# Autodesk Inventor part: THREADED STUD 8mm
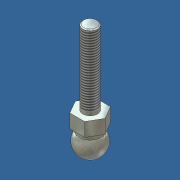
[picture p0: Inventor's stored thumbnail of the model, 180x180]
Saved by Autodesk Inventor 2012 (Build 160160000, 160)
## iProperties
Created: 2007-03
Part Number: THREADED STUD 8mm
Document SubType Name: Modeling
Designer: Andy Moles
Material: Steel
Mass: 40.6007 g
Surface Area: 22.6004 cm^2
Volume: 5.17207 cm^3
Density: 7.85 g/cm^3
Author: Andy Moles
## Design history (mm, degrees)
sketch "Sketch1"
  geometry: L1 (0, -7.5)-(0, 7.5); A1 r 7.5 centre (0, 0) between (0, -7.5) and (0, 7.5); 1 further point
  constraints: 2 end point, 2 point on circle, 1 centre point, 1 coincident, 1 midpoint, 1 vertical
  dimensions: "d5" = 15 distance of L1.start L1.end
revolve "Revolution1" sketch "Sketch1" stored, may be unused: angle "d1" = 90 deg
sketch "Sketch2"
  geometry: C1 r 6 at (0, 0); 1 further point
  constraints: 1 centre point, 1 coincident
  dimensions: "d2" = 12 diameter of C1
extrude "Extrusion1" join sketch "Sketch2" distance "d3" = 7; taper "d4" = 0 deg
sketch "Sketch3"
  geometry: L1 (-4.041, 7)-(4.041, 7); L2 (4.041, 7)-(8.083, 0); L3 (8.083, 0)-(4.041, -7); L4 (4.041, -7)-(-4.041, -7); L5 (-4.041, -7)-(-8.083, 0); L6 (-8.083, 0)-(-4.041, 7); C1 r 6 at (0, 0) reference; 1 further point
  constraints: 12 end point, 5 equal length, 1 horizontal, 1 horizontal alignment, 1 midpoint, 1 parallel, 1 vertical alignment
  dimensions: "d6" = 120 deg angle of L6 L5; "d7" = 120 deg angle of L1 L6; "d8" = 14 distance between parallel lines of L4 L1
extrude "Extrusion2" join sketch "Sketch3" distance "d9" = 7.5; taper "d10" = 0 deg
sketch "Sketch4"
  geometry: C1 r 4 at (0, 0); 1 further point
  constraints: 1 centre point, 1 coincident
  dimensions: "d11" = 8 diameter of C1
extrude "Extrusion3" join sketch "Sketch4" distance "d12" = 40.5; taper "d13" = 0 deg
thread "Thread1" dims "d14" = 38.5, "d15" = 2
chamfer "Chamfer1" distance "d16" = 0.5; stored, may be unused: second distance "d17" = 2, angle "d18" = 45 deg
body "Solid1"
